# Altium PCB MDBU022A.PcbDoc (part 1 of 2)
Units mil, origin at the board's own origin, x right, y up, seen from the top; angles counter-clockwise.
Board outline 3500 x 2200 mil, 2 copper layers (Top Layer, Bottom Layer), stack 64.8 mil thick; 115 components, 70 nets, 323 pads, 476 vias.
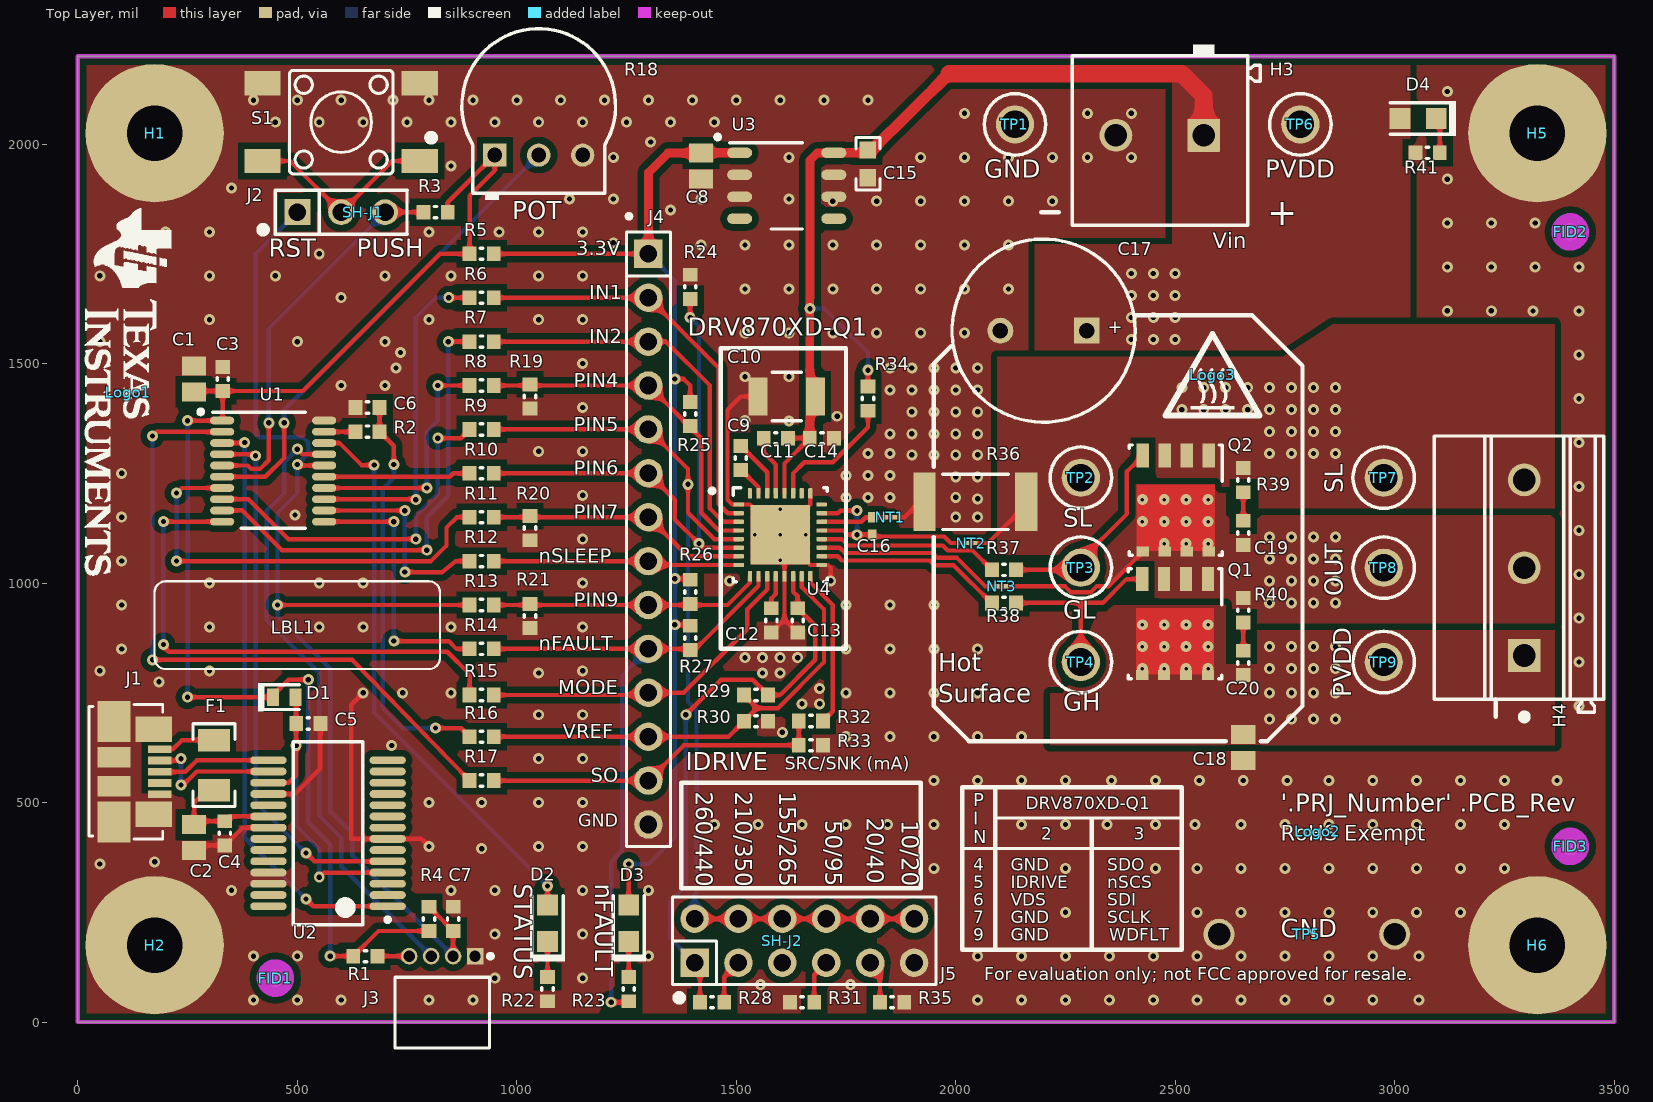
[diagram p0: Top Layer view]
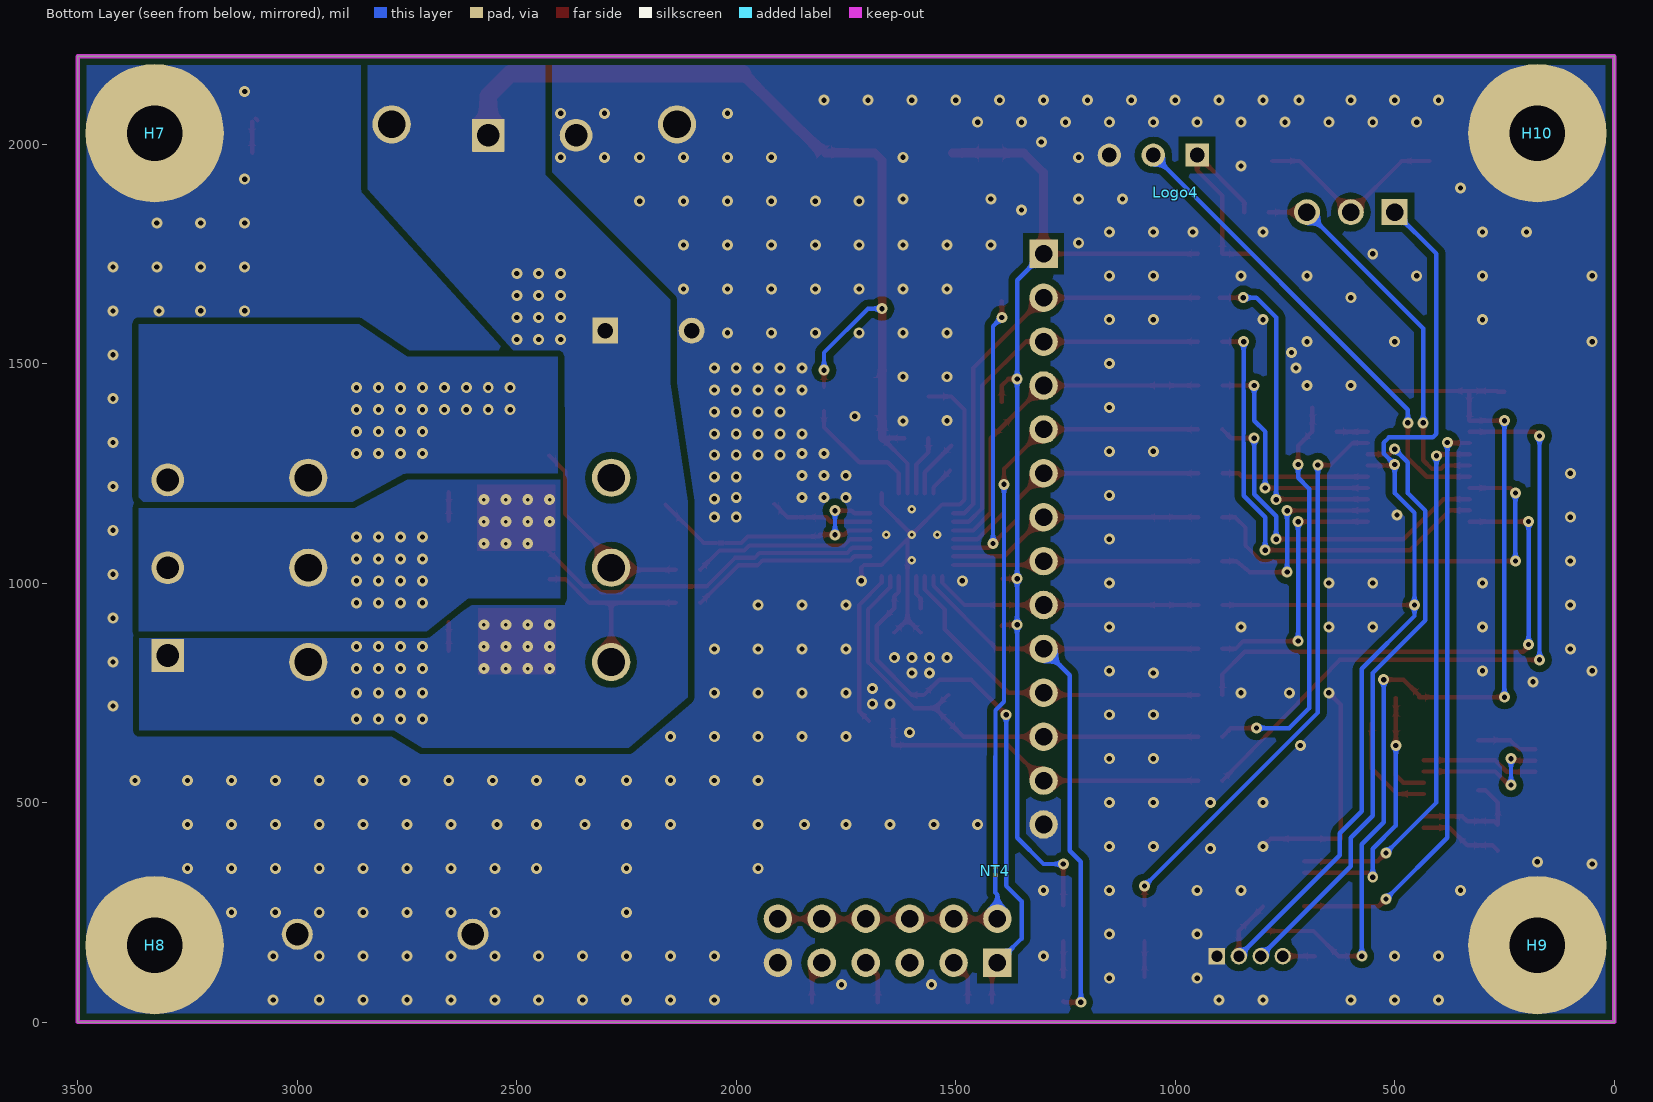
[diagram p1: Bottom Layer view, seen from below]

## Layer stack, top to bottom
Top Solder: solder mask 0.4, Solder Resist, Dk 3.5
Top Layer: signal copper 2.8
Dielectric1: core 59.2, FR-4, Dk 4.8
Bottom Layer: signal copper 2.8
Bottom Solder: solder mask 0.4, Solder Resist, Dk 3.5

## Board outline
0,0 0,2200 3500,2200 3500,0

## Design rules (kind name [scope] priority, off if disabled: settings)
AcuteAngle [All] p1: minimum=4.50000000000000E+0001 checktracksonly=FALSE
AssemblyTestPointUsage [All] p1: valid=2
Clearance Clearance_Keepouts [((IsTrack Or IsArc) And Not InPoly) And IsFree and IsKeepOut vs ((IsTrack Or IsArc) And Not InPoly) And IsFree and IsKeepOut] p1: gap=0
Clearance Clearance_BoardEdge_MountingHoles [OnCopper and InComponentClass('Mounting Holes') vs IsKeepOut] p2: gap=10
Clearance Clearance_BoardEdge_Poly [OnCopper and InPoly vs IsKeepOut] p3: gap=15
Clearance Clearance_BoardEdge [OnCopper and Not InComponentClass('Logo') and not InComponentClass('FiducialMark') and not InRegion(1000,500,4000,800) and Not IsKeepout vs IsKeepOut] p4: gap=15
Clearance Clearance_Poly [InPolygon] p5: gap=15
Clearance [All] p6: gap=7
ComponentClearance ComponentClearance_MountingHoles_FiducialMarks [InComponentClass('Mounting Holes') vs InComponentClass('FiducialMark')] p1: gap=10 collisioncheckmode=3 verticalgap=10 showdistances=FALSE
ComponentClearance ComponentClearance_Shunt [InComponentClass('Header') vs InComponentClass('Shunt')] p2: gap=0 collisioncheckmode=3 verticalgap=0 showdistances=FALSE
ComponentClearance ComponentClearance_Logo [InComponentClass('Logo')] p3: gap=10 collisioncheckmode=3 verticalgap=10 showdistances=FALSE
ComponentClearance ComponentClearance_ScrewToNut [(HasFootprint('NY PMS 440 0025 PH')) vs (HasFootprint('Keystone_1902C'))] p4: gap=5 collisioncheckmode=3 verticalgap=10 showdistances=FALSE
ComponentClearance ComponentClearance_MountingHoles [InComponentClass('Mounting Holes')] p5: gap=10 collisioncheckmode=3 verticalgap=100000 showdistances=FALSE
ComponentClearance ComponentClearance_SmallPassives [HasFootprint('0201*') or HasFootprint('0402*') or HasFootprint('0508') or HasFootprint('0603*') or HasFootprint('0612') or HasFootprint('0805*') or HasFootprint('0815*') or HasFootprint('0830*') or HasFootprint('1206*') or HasFootprint('1210*') or HasFootprint('1808*') or HasFootprint('1812*') or HasFootprint('1825*') or HasFootprint('2010*') or HasFootprint('2220*') or HasFootprint('2225*') or HasFootprint('2512*') or HasFootprint('2728*') or HasFootprint('3518*') vs HasFootprint('0201*') or HasFootprint('0402*') or HasFootprint('0508') or HasFootprint('0603*') or HasFootprint('0612') or HasFootprint('0805*') or HasFootprint('0815*') or HasFootprint('0830*') or HasFootprint('1206*') or HasFootprint('1210*') or HasFootprint('1808*') or HasFootprint('1812*') or HasFootprint('1825*') or HasFootprint('2010*') or HasFootprint('2220*') or HasFootprint('2225*') or HasFootprint('2512*') or HasFootprint('2728*') or HasFootprint('3518*')] p6: gap=10 collisioncheckmode=3 verticalgap=10 showdistances=FALSE
ComponentClearance ComponentClearance_THtoSMT [IsThruComponent vs IsSMTComponent] p7: gap=10 collisioncheckmode=3 verticalgap=10 showdistances=FALSE
ComponentClearance ComponentClearance_THtoTH [IsThruComponent vs IsThruComponent] p8: gap=10 collisioncheckmode=3 verticalgap=10 showdistances=FALSE
ComponentClearance [All] p9: gap=10 collisioncheckmode=3 verticalgap=10 showdistances=FALSE
DiffPairsRouting [All] p1: maxlimit=100 minlimit=10 mostfreqgap=10 toplayer_minwidth=15 toplayer_maxwidth=15 toplayer_prefwidth=15 bottomlayer_minwidth=15 bottomlayer_maxwidth=15 bottomlayer_prefwidth=15 maxuncoupledlength=1000
FabricationTestPointUsage TestPointUsage [All] p1: valid=2 allowmultiple=FALSE
FabricationTestpoint Testpoint [All] p1: side=3 testpointundercomponent=TRUE minsize=40 maxsize=100 preferedsize=60 minholesize=0 maxholesize=40 preferedholesize=32 testpointgrid=1 allowsidetop=TRUE allowsidebottom=TRUE usegrid=TRUE gridtolerance=0.01
FanoutControl Fanout_LCC [IsLCC] p1: bgadir=Out bgaviamode=Centered fanoutstyle=Auto fanoutdirection=Alternating viagrid=1 // Fanout_LCC (Default Rule)
FanoutControl Fanout_BGA [IsBGA] p2: bgadir=Out bgaviamode=Centered fanoutstyle=Auto fanoutdirection=Alternating viagrid=1 // Fanout_BGA (Default Rule)
FanoutControl Fanout_Default [All] p4: bgadir=Out bgaviamode=Centered fanoutstyle=Auto fanoutdirection=Alternating viagrid=1 // Fanout_Default (Default Rule)
FanoutControl Fanout_Small [(CompPinCount < 5)] p5: bgadir=Out bgaviamode=Centered fanoutstyle=Auto fanoutdirection=OutThenIn viagrid=1 // Fanout_Small (Default Rule)
HoleSize [All] p1: absolutevalues=TRUE maxlimit=251 minlimit=7 maxpercent=80.000 minpercent=20.000
MinimumAnnularRing MinimumAnnularRing_ThermalPadVias [IsVia and InAnyComponent] p1: minimumring=5.91
MinimumAnnularRing [All] p2: minimumring=5
MinimumSolderMaskSliver MinimumSolderMaskSliver_Logo [InComponentClass('Logo') vs InComponentClass('Logo')] p1: minsoldermaskwidth=0.7
MinimumSolderMaskSliver [All] p2: minsoldermaskwidth=3.94
PlaneConnect [All] p1: planeconnectstyle=Relief reliefexpansion=10 reliefentries=4 reliefconductorwidth=10 reliefairgap=10
PolygonConnect PolygonConnect_2 [All vs IsNamedPolygon('SL')] p1: connectstyle=Direct reliefconductorwidth=10 reliefentries=4 polygonreliefangle="90 Angle" airgapwidth=10
PolygonConnect PolygonConnect_1 [All vs IsNamedPolygon('SL')] p2: connectstyle=Relief reliefconductorwidth=10 reliefentries=4 polygonreliefangle="90 Angle" airgapwidth=10
PolygonConnect [All] p3: connectstyle=Direct reliefconductorwidth=10 reliefentries=4 polygonreliefangle="90 Angle" airgapwidth=10
RoutingVias ThermalPadVias [IsVia and InAnyComponent] p1: holewidth=7.87 width=19.68 viastyle="Through Hole" minholewidth=7 minwidth=19.68 maxholewidth=12.99 maxwidth=23.62
RoutingVias [All] p2: holewidth=16 width=34 viastyle="Through Hole" minholewidth=7 minwidth=25 maxholewidth=40 maxwidth=65
SilkToBoardRegionClearance [Not ((IsComment or IsDesignator) And (Hide <> 'False')) and not InRegion(1000,500,4000,800)] p1:
SilkToSilkClearance SilkToSilkClearance_Pb-FreeLogo [(HasFootprint('Pb-Free_Overlay_Medium') OR HasFootprint('Pb-Free_Overlay_Small')) vs (HasFootprint('Pb-Free_Overlay_Medium') OR HasFootprint('Pb-Free_Overlay_Small'))] p1: silktosilkclearance=0
SilkToSilkClearance [All] p2: silktosilkclearance=4
SilkToSolderMaskClearance SilkToComonentPadClearance [IsPad and InAnycomponent] p1: minsilkscreentomaskgap=5 clearancetoexposedcopper=TRUE
SilkToSolderMaskClearance "Silk to Solder Mask Opening" [All] p2: minsilkscreentomaskgap=4 clearancetoexposedcopper=FALSE
SolderMaskExpansion [All] p1: expansion=1.97
Width [All] p1: maxlimit=100 minlimit=6 preferedwidth=10 checkconnectedcopper=TRUE
15 further rules are at their usual default settings.

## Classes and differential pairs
component class Shunt: SH-J1 SH-J2
component class Header: J2 J4 J5
component class MDBU022: C1 C2 C3 C4 C5 C6 C7 C8 C9 C10 C11 C12 C13 C14 C15 C16 C17 C18 C19 C20 D1 D2 D3 D4 F1 H3 H4 J1 J2 J3 J4 J5 NT1 NT2 NT3 NT4 Q1 Q2 R1 R2 R3 R4 R5 R6 R7 R8 R9 R10 R11 R12 R13 R14 R15 R16 R17 R18 R19 R20 R21 R22 R23 R24 R25 R26 R27 R28 R29 R30 R31 R32 R33 R34 R35 R36 R37 R38 R39 R40 R41 S1 SH-J1 SH-J2 TP1 TP2 TP3 TP4 TP5 TP6 TP7 TP8 TP9 U1 U2 U3 U4
component class Label: LBL1
component class AssemblyNote: ZZ1 ZZ2 ZZ3 ZZ4
component class FiducialMark: FID1 FID2 FID3
component class MDBU022_Hardware: FID1 FID2 FID3 H1 H2 H5 H6 H7 H8 H9 H10 LBL1 Logo1 Logo2 Logo3 Logo4 ZZ1 ZZ2 ZZ3 ZZ4
component class Logo: Logo1
component class "Mounting Holes": H1 H2 H5 H6

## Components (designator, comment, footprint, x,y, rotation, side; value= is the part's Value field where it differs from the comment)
C1 "C2012X7R1A475M125AC" 0805L 265,1465 r90 top
C2 "C2012X7R1A475M125AC" 0805L 265,420 r270 top
C3 "C0603C104K8RACTU" 0603L 330,1465 r90 top
C4 "C0603C104K8RACTU" 0603L 335,430 r270 top
C5 "C0603C104K8RACTU" 0603L 525,680 r0 top
C6 "GRM188R70J105KA01D" 0603L 660,1400 r180 top
C7 "GRM188R71C102KA01D" 0603L 855,235 r90 top
C8 "JMK212BJ226KG-T" 0805L 1420,1950 r270 top
C9 "C1608X7R1H104K080AA" 0603L 1510,1285 r270 top
C10 "C3225X7S1H106K250AB" 1210_280 1615,1425 r180 top
C11 "C1608X7R1C105K080AC" 0603L 1590,1330 r0 top
C12 "GRM188R70J105KA01D" 0603L 1580,915 r90 top
C13 "GRM188R70J105KA01D" 0603L 1640,915 r270 top
C14 "C1608X7R1H104K080AA" 0603L 1695,1330 r0 top
C15 "C1608X7R1H104K080AA" 0603 1800,1955 r270 top
C16 "GRM155R71C102KA01D" 0402L 1810,1130 r90 top
C17 "ECA-1HM471" M_1000x2000 2200,1575 r180 top
C18 "GRM21BR71H105KA12L" 0805L 2655,625 r270 top
C19 "C1608X7R1H103K080AA" 0603L 2655,1114.45 r90 top
C20 "C1608X7R1H103K080AA" 0603L 2655,818.05 r90 top
D1 "CD0603-B0230" Diode_0603 470,740 r0 top
D2 "LTST-C171GKT" LED_LTST-C171 1070,225 r270 top
D3 "LTST-C170KRKT" LED_LTST-C170 1255,225 r270 top
D4 "LTST-C171GKT" LED_LTST-C171 3053.19,2058.27 r0 top
F1 "1206L050/15YR" 1206 310,585 r90 top
FID1 "Fiducial" Fiducial10-20 450,100 r0 top
FID2 "Fiducial" Fiducial10-20 3400,1800 r0 top
FID3 "Fiducial" Fiducial10-20 3400,400 r0 top
H1 "NY PMS 440 0025 PH" "NY PMS 440 0025 PH" 175,2025 r0 top
H2 "NY PMS 440 0025 PH" "NY PMS 440 0025 PH" 175,175 r0 top locked
H3 "1715721" PhoenixContact_1715721 2465,2020 r180 top
H4 "1715734" Phoenix_1715734 3295.15,1035 r90 top
H5 "NY PMS 440 0025 PH" "NY PMS 440 0025 PH" 3325,2025 r0 top
H6 "NY PMS 440 0025 PH" "NY PMS 440 0025 PH" 3325,175 r0 top
H7 "1902C" Keystone_1902C#1 3325,2025 r180 bottom locked
H8 "1902C" Keystone_1902C#1 3325,175 r180 bottom locked
H9 "1902C" Keystone_1902C#2 175.36,175 r180 bottom locked
H10 "1902C" Keystone_1902C#1 175,2025 r180 bottom locked
J1 "0473460001" CONN_47346-0001 25,570 r90 top
J2 "PEC03SAAN" CONN_PEC03SAAN 600,1845 r0 top
J3 "851-43-004-20-001000" CONN_851-43-004-20-001000 830,150 r0 top
J4 "TSW-114-07-G-S" TSW-114-07-G-S 1300,1100 r270 top
J5 "PEC06DAAN" CONN_PEC06DAAN 1655,185 r0 top
LBL1 "Size: 0.65\" x 0.20 \"" Label_650x200 500,904.1 r0 top
Logo1 "Texas Instruments" TI_Stacked_Overlay_Small 114.35,1435 r270 top
Logo2 "EU RoHS Exempt Logo" EURoHS_Exempt_60mil 2825,435 r0 top
Logo3 "CAUTION HOT SURFACE" IEC_HotSurface_Small 2585,1475 r0 top
Logo4 "FCC disclaimer" FCC_disclaimer 999.22,1890.48 r180 bottom
NT1 "Net-Tie" Net-Tie_10mil 1850.76,1150 r0 top net-tie
NT2 "Net-Tie" Net-Tie_10mil 2035,1091.25 r180 top net-tie
NT3 "Net-Tie" Net-Tie_10mil 2105,992.35 r0 top net-tie
NT4 "Net-Tie" Net-Tie_10mil 1410,345 r270 bottom net-tie
Q1 "CSD18540Q5B" TRANS_NexFET_Q5B 2499.65,899.79 r270 top
Q2 "CSD18540Q5B" TRANS_NexFET_Q5B 2501.18,1181.22 r270 top
R1 "CRCW06030000Z0EA" 0603L 655,150 r180 top
R2 "CRCW060310K0JNEA" 0603L 660,1345 r0 top
R3 "CRCW060347K0JNEA" 0603L 815,1845 r0 top
R4 "CRCW060347K0JNEA" 0603L 800,235 r270 top
R5 "CRCW06030000Z0EA" 0603L 920,1750 r180 top
R6 "CRCW06030000Z0EA" 0603L 920,1650 r180 top
R7 "CRCW06030000Z0EA" 0603L 920,1550 r180 top
R8 "CRCW06030000Z0EA" 0603L 920,1450 r180 top
R9 "CRCW06030000Z0EA" 0603L 920,1350 r180 top
R10 "CRCW06030000Z0EA" 0603L 920,1250 r180 top
R11 "CRCW06030000Z0EA" 0603L 920,1150 r180 top
R12 "CRCW06030000Z0EA" 0603L 920,1050 r180 top
R13 "CRCW06030000Z0EA" 0603L 920,950 r180 top
R14 "CRCW06030000Z0EA" 0603L 920,850 r180 top
R15 "CRCW06030000Z0EA" 0603L 920,745 r180 top
R16 "CRCW06030000Z0EA" 0603L 920,650 r180 top
R17 "CRCW06030000Z0EA" 0603L 920,550 r180 top
R18 "3352T-1-503LF" Bourns_3352T 1050,1975 r0 top
R19 "CRCW06030000Z0EA" 0603L 1030,1425 r90 top
R20 "CRCW06030000Z0EA" 0603L 1030,1125 r90 top
R21 "CRCW06030000Z0EA" 0603L 1030,925 r90 top
R22 "CRCW0603330RJNEA" 0603L 1070,75 r90 top
R23 "CRCW0603330RJNEA" 0603L 1255,75 r90 top
R24 "CRCW06030000Z0EA" 0603L 1395,1675 r270 top
R25 "RC0603JR-07750RL" 0603L 1395,1385 r90 top
R26 "CRCW060310K0JNEA" 0603L 1395,980 r270 top
R27 "CRCW060310K0JNEA" 0603L 1395,875 r270 top
R28 "CRCW060368K0JNEA" 0603L 1445,45 r180 top
R29 "CRCW06030000Z0EA" 0603L 1545,745 r180 top
R30 "CRCW06030000Z0EA" 0603L 1545,685 r0 top
R31 "CRCW0603200KJNEA" 0603L 1650,45 r0 top
R32 "CRCW06037K50FKEA" 0603L 1670,685.67 r180 top
R33 "CRCW060310K0FKEA" 0603L 1670,630.67 r180 top
R34 "CRCW06030000Z0EA" 0603L 1800,1420 r270 top
R35 "CRCW060333K0JNEA" 0603L 1855,45 r180 top
R36 "CSR2512C0R01F" 2512 2045,1185 r0 top
R37 "CRCW06030000Z0EA" 0603L 2110,1030 r0 top
R38 "CRCW06030000Z0EA" 0603L 2110,954.7 r0 top
R39 "RT0603BRD07100RL" 0603L 2655,1234.45 r270 top
R40 "RT0603BRD07100RL" 0603L 2655,938.05 r270 top
R41 "CRCW06034K99FKEA" 0603L 3075,1980 r0 top
S1 "FSM4JSMA" SW_FSM4JSMA 600,2050 r270 top
SH-J1 "969102-0000-DA" SNT-100-BK-G 650,1845 r180 top
SH-J2 "969102-0000-DA" SNT-100-BK-G 1605,185 r90 top
TP1 "5006" Keystone5006 2135,2045 r0 top
TP2 "5007" Keystone5007 2285,1240 r0 top
TP3 "5007" Keystone5007 2285,1035 r0 top
TP4 "5007" Keystone5007 2285,820 r0 top
TP5 "D3082-05" Harwin_D3082-05 2800,200 r180 top
TP6 "5005" Keystone5005 2785,2045 r0 top
TP7 "5007" Keystone5007 2975,1240 r90 top
TP8 "5007" Keystone5007 2975,1035 r90 top
TP9 "5005" Keystone5005 2975,820 r90 top
U1 "MSP430G2553IPW20" PW0020A_N 445,1255 r0 top
U2 "FT232RL" SSOP28_N 570,430 r180 top
U3 "LM9036QMX-3.3/NOPB" D0008A_N 1615,1905 r0 top
U4 "DRV8702DQRHBRQ1" RHB0032E 1600,1110 r0 top
ZZ1 "This Assembly Note is for PCB labels only" AssemblyNoteLabel 185,2598 r0 top
ZZ2 "This Assembly Note will show in the PcbDoc and associated outputs" AssemblyNote 185,2489.11 r0 top
ZZ3 "This Assembly Note will show in the PcbDoc and associated outputs" AssemblyNote 185,2400.56 r0 top
ZZ4 "This Assembly Note will show in the PcbDoc and associated outputs" AssemblyNote 185,2312 r0 top

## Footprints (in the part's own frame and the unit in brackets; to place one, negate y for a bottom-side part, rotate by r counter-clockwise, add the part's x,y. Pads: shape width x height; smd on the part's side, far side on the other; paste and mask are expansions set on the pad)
0402L [mm] "0402 from SM-752 data"
  rect 0.6x0.5 smd: 1(-0.5,0) 2(0.5,0)
  body extent -0.55,-0.3 0.55,0.3, height 0.6
0603 [mm] "0603 from SM-752 data"
  rect 1x0.95 smd: 1(-0.8,0) 2(0.8,0)
  silkscreen extent -1.52,-0.69 1.52,0.69, body extent -0.87,-0.47 0.87,0.47, height 1
0603L [mm] "0603 from SM-752 data"
  rect 0.8x0.85 smd: 1(-0.7,0) 2(0.7,0)
  silkscreen extent -0.07,-0.33 0.07,0.33, body extent -0.87,-0.47 0.87,0.47, height 1
0805L [mm] "0805 from SM-752 data"
  rect 1.1x1.4 smd: 1(-0.75,0) 2(0.75,0)
  body extent -1.1,-0.72 1.1,0.72, height 1.45
1206 [mm] "1206 from SM-752 data"
  rect 1.3x1.85 smd: 1(-1.45,0) 2(1.45,0)
  silkscreen extent -2.4,-1.21 2.4,1.21, body extent -1.7,-0.9 1.7,0.9, height 1.35
1210_280 [mm] "SMD, 2-Leads, Body 3.6x2.8mm, Height 2.8mm"
  rect 1.1x2.2 smd: 1(-1.65,0) 2(1.65,0)
  silkscreen extent -0.84,-1.4 0.84,1.4, body extent -1.8,-1.4 1.8,1.4, height 2.8
2512 [mm] "Chip Resistor, Body 6.3x3.2mm, IPC Medium Density"
  rect 1.3x3.4 smd: 1(-2.95,0) 2(2.95,0)
  silkscreen extent -1.9,-1.6 1.9,1.6, body extent -3.22,-1.67 3.22,1.67, height 0.71
AssemblyNote [mil] "Assembly Note"
AssemblyNoteLabel [mil] "Assembly Note for PCB Labels"
Bourns_3352T [mm] "TH, 3-Leads, Body 9.53x8.89mm, Pitch 2.54mm"
  rect 1.35x1.35 hole 0.85: 1(-2.54,0)
  round 1.35 hole 0.85: 2(0,0) 3(2.54,0)
  silkscreen extent -4.44,-2.6 4.44,7.31, body extent -4.44,-2.21 4.45,7.32, height 3.81
CONN_851-43-004-20-001000 [mm] "MILL-MAX"
  rect 0.95x0.95 hole 0.65: 1(1.905,0)
  round 0.95 hole 0.65: 2(0.635,0) 3(-0.635,0) 4(-1.905,0)
  silkscreen extent -2.73,-5.31 2.73,-1.22, body extent -2.73,-5.31 2.73,0.23, height 2.23
CONN_47346-0001 [mm] "MOLEX"
  rect 0.45x1.38 smd: 1(1.3,-4.105) 2(0.65,-4.105) 3(0,-4.105) 4(-0.65,-4.105) 5(-1.3,-4.105)
  rect 1.475x2.1 smd: 6(-2.462,-3.755) 11(2.463,-3.75)
  rect 2.375x1.9 smd: 7(-2.912,-1.45) 10(2.912,-1.45)
  rect 1.175x1.9 smd: 8(-0.837,-1.45) 9(0.837,-1.45)
  silkscreen extent -3.9,-4.28 3.9,0, body extent -3.99,-4.43 3.99,1, height 2.72
CONN_PEC03SAAN [mm] "SULLINS"
  rect 1.5x1.5 hole 1.016: 1(-2.54,0)
  round 1.5 hole 1.016: 2(0,0) 3(2.54,0)
  silkscreen extent -4.72,-1.27 3.81,1.27, body extent -3.84,-1.3 3.84,1.3, height 8.38
CONN_PEC06DAAN [mm] "SULLINS"
  rect 1.65x1.65 hole 1.016 mask+0: 1(-6.35,-1.27)
  round 1.65 hole 1.016 mask+0: 2(-6.35,1.27) 3(-3.81,-1.27) 4(-3.81,1.27) 5(-1.27,-1.27) 6(-1.27,1.27) 7(1.27,-1.27) 8(1.27,1.27) 9(3.81,-1.27) 10(3.81,1.27) 11(6.35,-1.27) 12(6.35,1.27)
  silkscreen extent -7.62,-3.51 7.62,2.54, body extent -7.62,-2.54 7.62,2.54, height 8.38
D0008A_N [mm] "SOIC, 8-Leads, Body 4.9x3.9mm, Pitch 1.27mm, IPC Medium Density"
  oval 1.45x0.6 smd: 1(-2.725,1.905) 2(-2.725,0.635) 3(-2.725,-0.635) 4(-2.725,-1.905) 5(2.725,-1.905) 6(2.725,-0.635) 7(2.725,0.635) 8(2.725,1.905)
  silkscreen extent -3.3,-2.5 0.9,2.5, body extent -3,-2.45 3,2.45, height 1.63
Diode_0603 [mm] "Based on Bourns recommended land pattern Rev 10/09"
  rect 0.7x1 smd: 1(-0.65,0) 2(0.65,0)
  silkscreen extent -1.5,-0.8 0.9,0.8, body extent -0.9,-0.5 0.9,0.5, height 0.85
EURoHS_Exempt_60mil [mil] "EU RoHS Exempt symbol"
FCC_disclaimer [mil]
Fiducial10-20 [mm]
  round 1 smd mask+0.5: 1(0,0)
  Top Layer keep-out circle w1.178: c0,0 r0.5
Harwin_D3082-05 [mm] "Shorting Plug, 10.16mm spacing, TH"
  round 1.8 hole 1.3: 1(-5.08,0) 2(5.08,0)
  body extent -5.6,-0.52 5.61,0.52, height 6.63
IEC_HotSurface_Small [mil]
  silkscreen extent -107,-93 107,92
Keystone5005 [mil] "Keystone Compact loops"
  round 87 hole 63: 1(0,0)
  silkscreen extent -70,-70 70,70, body extent -63,-63 62,63, height 225
Keystone5006 [mil] "Keystone Compact loops"
  round 87 hole 63: 1(0,0)
  silkscreen extent -70,-70 70,70, body extent -63,-63 62,63, height 225
Keystone5007 [mil] "Keystone Compact loops"
  round 87 hole 63: 1(0,0)
  silkscreen extent -70,-70 70,70, body extent -63,-63 62,63, height 225
Keystone_1902C#1 [mil] "Hex Standoff, 4-40 threaded, nylon"
  body extent -145,-126 146,126, height 501
Keystone_1902C#2 [mil] "Hex Standoff, 4-40 threaded, nylon"
  round 1 on Mech4: 0(0,0)
  body extent -145,-126 146,126, height 501
Label_650x200 [mil] "Thermal Transfer Label"
  silkscreen extent -325,-100 325,100, body extent -325,-100 325,100, height 1
LED_LTST-C170 [mm] "LITE-ON"
  rect 1.2x1.2 smd: 1(-1.05,0) 2(1.05,0)
  silkscreen extent -1.6,-1 2.2,1, body extent -1.05,-0.67 1.05,0.67, height 1.1
LED_LTST-C171 [mm] "LITE-ON"
  rect 1.2x1.2 smd: 1(-1.05,0) 2(1.05,0)
  silkscreen extent -1.6,-1 2.2,1, body extent -1.05,-0.67 1.05,0.67, height 0.8
M_1000x2000 [mm] "Panasonic"
  rect 1.5x1.5 hole 0.9: 1(-2.5,0)
  round 1.5 hole 0.9: 2(2.5,0)
  silkscreen extent -5.3,-5.3 5.3,5.3, body extent -5.21,-5.24 5.24,5.24, height 22.01
Net-Tie_10mil [mil] "10mil net tie, no solder mask opening, no solder paste"
  rect 10x10 smd paste-5 mask-5: 1(-10,0) 2(10,0)
  Top Layer region: -6,5 6,5 6,-5 -6,-5
"NY PMS 440 0025 PH" [mm] "4-40 nylon screw and mounting hole"
  round 8 hole 3.2: 1(0,0)
  body extent -3.3,-3.3 3.3,3.3, height 2.69
Phoenix_1715734 [mm] "Phoenix"
  rect 1.9x1.9 hole 1.321: 1(-5.08,0)
  round 1.9 hole 1.321: 2(0,0) 3(5.08,0)
  silkscreen extent -8.76,-4.6 7.62,5.2, body extent -8.36,-4.6 7.62,5.2, height 14.2
PhoenixContact_1715721 [mm] "Phoenix Contact 1715721 used on LM3445 design from Longmont"
  rrect5% 1.905x1.905 hole 1.3: 1(-2.54,0)
  round 1.9 hole 1.3: 2(2.54,0)
  silkscreen extent -5.82,-5.25 5.08,5.2, body extent -5.82,-4.6 5.08,5.2, height 14.2
PW0020A_N [mm] "TSOP, 20-Leads, Body 6.5x4.4mm, Pitch 0.65mm, IPC Medium Density"
  oval 1.4x0.45 smd: 1(-2.95,2.925) 2(-2.95,2.275) 3(-2.95,1.625) 4(-2.95,0.975) 5(-2.95,0.325) 6(-2.95,-0.325) 7(-2.95,-0.975) 8(-2.95,-1.625) 9(-2.95,-2.275) 10(-2.95,-2.925) 11(2.95,-2.925) 12(2.95,-2.275) 13(2.95,-1.625) 14(2.95,-0.975) 15(2.95,-0.325) 16(2.95,0.325) 17(2.95,0.975) 18(2.95,1.625) 19(2.95,2.275) 20(2.95,2.925)
  silkscreen extent -3.5,-3.3 1.85,3.4, body extent -3.21,-3.25 3.21,3.25, height 1
RHB0032E [mm] "QFN, 32-Leads, Body 5x5mm, Pitch 0.5mm, Thermal Pad 3.45x3.45mm, TI Recommended"
  rrect40% 0.6x0.25 smd: 1(-2.4,1.75) 2(-2.4,1.25) 3(-2.4,0.75) 4(-2.4,0.25) 5(-2.4,-0.25) 6(-2.4,-0.75) 7(-2.4,-1.25) 8(-2.4,-1.75) 17(2.4,-1.75) 18(2.4,-1.25) 19(2.4,-0.75) 20(2.4,-0.25) 21(2.4,0.25) 22(2.4,0.75) 23(2.4,1.25) 24(2.4,1.75)
  rrect40% 0.25x0.6 smd: 9(-1.75,-2.4) 10(-1.25,-2.4) 11(-0.75,-2.4) 12(-0.25,-2.4) 13(0.25,-2.4) 14(0.75,-2.4) 15(1.25,-2.4) 16(1.75,-2.4) 25(1.75,2.4) 26(1.25,2.4) 27(0.75,2.4) 28(0.25,2.4) 29(-0.25,2.4) 30(-0.75,2.4) 31(-1.25,2.4) 32(-1.75,2.4)
  rrect3% 3.45x3.45 smd paste-1.725: 33(0,0)
  rrect7% 1.49x1.49 on Top Paste: ""(-0.845,-0.845) ""(-0.845,0.845) ""(0.845,-0.845) ""(0.845,0.845)
  silkscreen extent -2.72,-2.73 2.72,2.73, body extent -2.57,-2.57 2.58,2.58, height 1.01
SNT-100-BK-G [mil] "Samtec STEP model"
  round 1 on Mech3: 0(0,0)
  body extent -100,-50 100,50, height 344
SSOP28_N [mm] "SOP, 28-Leads, Body 10.2x5.3mm, Pitch 0.65mm, IPC Medium Density"
  oval 2.1x0.45 smd: 1(-3.45,4.225) 2(-3.45,3.575) 3(-3.45,2.925) 4(-3.45,2.275) 5(-3.45,1.625) 6(-3.45,0.975) 7(-3.45,0.325) 8(-3.45,-0.325) 9(-3.45,-0.975) 10(-3.45,-1.625) 11(-3.45,-2.275) 12(-3.45,-2.925) 13(-3.45,-3.575) 14(-3.45,-4.225) 15(3.45,-4.225) 16(3.45,-3.575) 17(3.45,-2.925) 18(3.45,-2.275) 19(3.45,-1.625) 20(3.45,-0.975) 21(3.45,-0.325) 22(3.45,0.325) 23(3.45,0.975) 24(3.45,1.625) 25(3.45,2.275) 26(3.45,2.925) 27(3.45,3.575) 28(3.45,4.225)
  silkscreen extent -3.57,-5.3 2,5.3, body extent -2.7,-5.3 2.7,5.3, height 2
SW_FSM4JSMA [mm] "Alcoswitch"
  rect 1.4x2.1 smd: 1(2.25,4.55) 2(2.25,-4.55) 3(-2.25,4.55) 4(-2.25,-4.55)
  silkscreen extent -3,-3 3,5.4, body extent -3,-5 3,5, height 5.1
TI_Stacked_Overlay_Small [mil]
  silkscreen extent -418,-98 418,98
TRANS_NexFET_Q5B [mm] "TI recommended land pattern (nominal) November 2012"
  rect 1.372x0.71 smd paste-0.4: 1(-2.776,1.905) 2(-2.776,0.635) 3(-2.776,-0.635) 4(-2.776,-1.905)
  rect 0.59x0.71 smd paste-0.3: 5(2.776,-1.905) 6(2.776,-0.635) 7(2.776,0.635) 8(2.776,1.905)
  Top Layer region: -1.105,-2.259 2.745,-2.259 2.745,2.261 -1.105,2.261
  silkscreen extent -3.38,-2.7 3,2.7, body extent -3.23,-2.55 2.87,2.55, height 1.06
TSW-114-07-G-S [mm] "Samtec 100mil, 1x14, 230 mil above insulator"
  rect 1.65x1.65 hole 1.016 mask+0: 1(-16.51,0)
  round 1.65 hole 1.016 mask+0: 2(-13.97,0) 3(-11.43,0) 4(-8.89,0) 5(-6.35,0) 6(-3.81,0) 7(-1.27,0) 8(1.27,0) 9(3.81,0) 10(6.35,0) 11(8.89,0) 12(11.43,0) 13(13.97,0) 14(16.51,0)
  silkscreen extent -18.8,-1.27 17.78,1.27, body extent -17.78,-1.27 17.78,1.27, height 8.38

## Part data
C1 C2: "CAP, CERM, 4.7 µF, 10 V, +/- 20%, X7R, 0805"
C3 C4 C5: "CAP, CERM, 0.1 µF, 10 V, +/- 10%, X7R, 0603"
C6 C12 C13: "CAP, CERM, 1 µF, 6.3 V, +/- 10%, X7R, 0603"
C7: "CAP, CERM, 1000 pF, 16 V, +/- 10%, X7R, 0603"
C8: "CAP, CERM, 22 µF, 6.3 V, +/- 10%, X5R, 0805"
C9 C14 C15: "CAP, CERM, 0.1 µF, 50 V, +/- 10%, X7R, 0603"
C10: "CAP, CERM, 10 µF, 50 V, +/- 10%, X7S, 1210"
C11: "CAP, CERM, 1 µF, 16 V, +/- 10%, X7R, 0603"
C16: "CAP, CERM, 1000 pF, 16 V, +/- 10%, X7R, 0402"
C17: "CAP, AL, 470 µF, 50 V, +/- 20%, TH"
C18: "CAP, CERM, 1 µF, 50 V, +/- 10%, X7R, 0805"
C19 C20: "CAP, CERM, 0.01 µF, 50 V, +/- 10%, X7R, 0603"
D1: "Diode, Schottky, 35 V, 0.2 A, 0603 Diode"
D2 D4: "LED, Green, SMD"
D3: "LED, Red, SMD"
F1: "Fuse, 100 A, 15 VDC, SMD"
FID1 FID2 FID3: "Fiducial mark.  There is nothing to buy or mount."
H1 H2 H5 H6: "Machine Screw, Round, #4-40 x 1/4, Nylon, Philips panhead"
H3: "Terminal Block, 5.08 mm, 2x1, TH"
H4: "TERM BLOCK 3POS 5.08MM, TH"
H7 H8 H9 H10: "Standoff, Hex, 0.5\"L #4-40 Nylon"
J1: "Connector, Receptacle, Micro-USB Type B, R/A, Bottom Mount SMT"
J2: "Header, 100mil, 3x1, Tin, TH"
J3: "SOCKET .050\" GRID SIP 4 POS R/A, TH"
J4: "Header, 100mil, 14x1, Gold, TH"
J5: "Header, 100mil, 6x2, Tin, TH"
LBL1: library part THT-14-423-10, "Thermal Transfer Printable Labels, 0.650\" W x 0.200\" H - 10,000 per roll"
Logo1: library part TI_Logo, "Texas Instrument Corporate Signature"
Logo2: library part EURoHS_Exempt
Logo3: library part IEC_HotSurface, "IEC 61010-1 Hot Surface Warning"
Logo4: library part FCC_disclaimer, "FCC_disclaimer"
NT1 NT2 NT3 NT4: "Single point connection between nets."
Q1 Q2: "MOSFET, N-CH, 60 V, 28 A, SON 5x6mm"
R1 R5 R6 R7 R8 R9 R10 R11 R12 R13 R14 R15 R16 R17 R19 R20 R21 R24 R29 R30 R34 R37 R38: "RES, 0, 5%, 0.1 W, 0603"
R2 R26 R27: "RES, 10 k, 5%, 0.1 W, 0603"
R3 R4: "RES, 47 k, 5%, 0.1 W, 0603"
R18: "Trimming Potentiometer, 50K, 0.5W, TH"
R22 R23: "RES, 330, 5%, 0.1 W, 0603"
R25: "RES, 750, 5%, 0.1 W, 0603"
R28: "RES, 68 k, 5%, 0.1 W, 0603"
R31: "RES, 200 k, 5%, 0.1 W, 0603"
R32: "RES, 7.50 k, 1%, 0.1 W, 0603"
R33: "RES, 10.0 k, 1%, 0.1 W, 0603"
R35: "RES, 33 k, 5%, 0.1 W, 0603"
R36: "RES, 0.01, 1%, 3 W, AEC-Q200 Grade 0, 2512"
R39 R40: "RES, 100, 0.1%, 0.1 W, 0603"
R41: "RES, 4.99 k, 1%, 0.1 W, 0603"
S1: "Switch, Tactile, SPST-NO, 0.05A, 12V, SMT"
SH-J1 SH-J2: "Shunt, 100mil, Gold plated, Black"
TP1: "Test Point, Compact, Black, TH"
TP2 TP3 TP4 TP7 TP8: "Test Point, Compact, White, TH"
TP5: "1mm Uninsulated Shorting Plug, 10.16mm spacing, TH"
TP6 TP9: "Test Point, Compact, Red, TH"
U1: "16 MHz Mixed Signal Microcontroller with 16 KB Flash, 512 B SRAM and 24 GPIOs, -40 to 85 degC, 20-pin SOP (PW), Green (RoHS & no Sb/Br)"
U2: "USB to Serial UART, SSOP28"
U3: "Ultra-Low Quiescent Current Voltage Regulator, D0008A"
U4: "Automotive Half H-Bridge Gate Driver, RHB0032E (VQFN-32)"
ZZ1: library part AssemblyNoteLabel
ZZ2 ZZ3 ZZ4: library part AssemblyNote

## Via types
v1: diameter 25, hole 12, Top Layer to Bottom Layer, tented both sides, 446 vias
v2: diameter 25, hole 7.82, Top Layer to Bottom Layer, tented both sides, 23 vias
v3: diameter 19.68, hole 7.87, Top Layer to Bottom Layer, 5 vias
v4: diameter 25, hole 12, Top Layer to Bottom Layer, 2 vias

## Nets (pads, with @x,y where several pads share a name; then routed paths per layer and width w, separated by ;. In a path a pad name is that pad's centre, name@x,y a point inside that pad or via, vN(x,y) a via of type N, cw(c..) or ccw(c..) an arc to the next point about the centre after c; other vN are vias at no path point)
3.3V: C8.1 D3.1 J4.1 R5.1 R25.2 R26.1 R27.1 U3.1 | length 2488.9
  Top Layer w10: R5.1@948.05,1750 J4.1@1300,1750 ; D3.1@1255,266.34 v1(1255,360) ; v1(1360,905) 1392.56,905 R27.1@1395,902.56 ; v1(1360,1010) R26.1@1392.56,1010 ; v1(1360,1465) 1380,1465 1395,1450 R25.2@1395,1412.56 ; C8.1@1420,1979.53 C8.1@1420.47,1980
  Top Layer w20: J4.1@1300,1750 1300,1935 1344.53,1979.53 C8.1@1420,1979.53 ; C8.1@1420.47,1980 U3.1@1507.72,1980
  Bottom Layer w10: v1(1255,360) 1300,360 1360,420 v1(1360,905) v1(1360,1010) v1(1360,1465) 1360,1690 J4.1@1300,1750
3.3V_COM: C5.1 D1.2 U2.4 U2.17 | length 728.1
  Top Layer w10: U2.17@434.17,545.16 480.16,545.16 497.44,562.44 v1(497.44,630) C5.1@497.44,680 D1.2@497.44,738.15 ; v1(550,330) 560.43,340.43 U2.4@705.83,340.43
  Bottom Layer w10: v1(497.44,630) 497.44,447.56 550,395 v1(550,330)
3.3V_MCU: C1.1 C3.1 D1.1 R1.2 R3.2 R4.2 R5.2 R18.1 U1.1 | length 3164.6
  Top Layer w10: v1(250,740) D1.1@444.41,740 444.41,744.41 480,780 v1(525,780) ; v1(250,1370) U1.1@328.7,1370 ; C1.1@250,1435.47 C1.1@265,1435.47 266.97,1437.44 C3.1@330,1437.44 ; U1.1@330,1371.3 C3.1@330,1437.44 ; v1(575,150) R1.2@627.44,150 684.88,207.44 R4.2@800,207.44 ; R3.2@842.56,1845 842.56,1867.56 R18.1@950,1975 950,1940 892.44,1882.44 R5.2@892.44,1750 825,1750 512.44,1437.44 C3.1@330,1437.44
  Bottom Layer w10: v1(250,740) v1(250,1370) ; v1(525,780) 525,455 575,405 v1(575,150)
5V_USB: C2.1 C4.1 F1.1 U2.20 | length 284
  Top Layer w10: F1.1@310,527.91 292.91,527.91 265,500 C2.1@265,449.53 273.03,457.56 C4.1@335,457.56 345.83,468.39 U2.20@434.17,468.39
AVDD: C13.1 J5.1 R28.2 R29.1 U4.14 | length 1284.6
  Top Layer w10: v1(1385,700) 1465,780 1537.56,780 R29.1@1572.56,745 1600,745 1680,825 1680,902.56 C13.1@1640,942.56 1640,970 1629.53,980.47 U4.14@1629.53,1015.51 ; J5.1@1405,135 1417.44,122.56 R28.2@1417.44,45
  Bottom Layer w10: v1(1385,700) 1385,310 1350,275 1350,190 J5.1@1405,135
DM: J1.2 U2.16 | length 333.7
  Top Layer w10: J1.2@180,595.59 230.59,595.59 v1(235,600) ; v1(235,540) 240.28,540 271.03,570.75 U2.16@434.17,570.75
  Bottom Layer w10: v1@235,535 v1(235,540) v1(235,600)
DP: J1.3 U2.15 | length 265.1
  Top Layer w10: J1.3@180,570 245,570 271.34,596.34 U2.15@434.17,596.34
DVDD: C12.2 U4.12 | length 77.2
  Top Layer w10: C12.2@1580,942.56 1580,965 1590.16,975.16 U4.12@1590.16,1015.51
GH: R38.1 U4.18 | length 431.9
  Top Layer w10: U4.18@1694.49,1060.79 1731.13,1060.79 1740.42,1051.5 1940.42,1051.5 1951.67,1040.25 1995.71,1040.25 2081.25,954.7 R38.1@2082.44,954.7
GL: R37.1 U4.20 | length 417
  Top Layer w10: U4.20@1694.49,1100.16 1739.84,1100.16 1754.5,1085.5 1970.46,1085.5 1981.71,1074.25 2038.19,1074.25 R37.1@2082.44,1030
GND: C1.2 C2.2 C3.2 C4.2 C5.2 C6.2 C7.2 C8.2 C10.2 C12.1 C13.2 C14.2 C15.2 C17.2 C18.2 H1.1 H2.1 H3.2 H5.1 H6.1 J1.5 J1.6 J1.7 J1.8 J1.9 J1.10 J1.11 J3.1 J4.14 J5.11 NT1.2 R18.3 R19.1 R20.1 R21.1 R22.1 R24.1 R30.2 R31.1 R33.1 R35.1 R36.1 R41.1 S1.3 S1.4 TP1.1 TP5.1 TP5.2 U1.20 U2.7 U2.18 U2.21 U2.25 U2.26 U3.2 U3.3 U3.6 U3.7 U4.1 U4.13 U4.17 U4.25 U4.33 | length 2048
  Top Layer w10: C2.2@265,390.47 276.97,402.44 C4.2@335,402.44 375.35,442.8 U2.21@434.17,442.8 ; U2.18@434.17,519.57 494.57,519.57 552.56,577.56 C5.2@552.56,680 ; v1(650,750) 622.8,722.8 622.8,417.2 U2.7@705.83,417.2 782.8,417.2 v1(800,400) ; C10.2@1561.85,1425 1510,1425 1480,1395 1480,1190 1491.1,1178.9 1531.1,1178.9 v3(1600,1110) ; C12.1@1580,887.44 1609.84,917.28 ; C13.2@1640,887.44 1639.69,887.44 1609.84,917.28 ; U4.25@1668.9,1204.49 1668.9,1178.9 v3(1600,1110) ; v1(1715,1005) 1715,1035 1708.9,1041.1 U4.17@1694.49,1041.1 1668.9,1041.1 U4.33@1609.84,1100.16 ; NT1.2@1860.76,1150 1883.17,1150 R36.1@1913.17,1180 ; v3(1600,1110) U4.33@1609.84,1100.16 ; 1609.84,917.28 U4.13@1609.84,1015.51 U4.33@1609.84,1100.16
  other v1: 400,50 500,50 600,50 800,50 900,50 2050,50 2150,50 2250,50 2350,50 2450,50 2550,50 2650,50 3055,50 2750,50.67 2850,50.67 2950,50.67 1555,85 1760,85 950,100 1150,100 400,150 500,150 1300,150 2050,150 2150,150 2250,150 2350,150 2450,150 2550,150 2650,150 2750,150 2850,150 2950,150 3055,150 950,200 1150,200 2250,250 2550,250 2650,250 2750,250 2850,250 2950,250 3050,250 3150,250 350,300 850,300 950,300 1150,300 1300,300 1950,350 2250,350 2455,350 2550,350 2650,350 2750,350 2850,350 2950,350 3050,350 3150,350 3250,350 50,360 175,365 920,395 1050,400 1150,400 1450,450 1550,450 1650,450 1750,450 1845,450 1950,450 2150,450 2250,450 2345,450 2455,450 2545,450 2650,450 2750,450 2850,450 2950,450 3050,450 3150,450 3250,450 800,500 920,500 1050,500 1150,500 1950,550 2050,550 2355,550 2455,550 2555,550 2655,550 2755,550 2850,550 2950,550 3050,550 3150,550 3250,550 3370,550 2150,550.67 2250,550.67 1050,600 1150,600 715,630 1750,650 1850,650 1950,650 2050,650 2150,650 1605,660 1050,700 1150,700 3420,720 1650,725 1690,725 740,750 850,750 1750,750 1850,750 1950,750 2050,750 1690,760 185,775 1050,795 1560,795 1600,795 50,800 300,800 1150,800 3420,820 1520,830 1560,830 1600,830 1640,830 100,850 1750,850 1850,850 1950,850 2050,850 300,900 550,900 650,900 850,900 1150,900 3420,920 100,950 1750,950 1850,950 1950,950 300,1000 550,1000 650,1000 1150,1000 1485,1005 3420,1020 100,1050 1150,1100 3420,1120 100,1150 2000,1150 2050,1150 495,1155 2050,1192.01 1750.51,1194.53 1800,1195 1850,1195 2000,1195.24 1150,1200 3420,1220 2000,1242.01 2050,1242.01 1750.51,1244.53 1800,1245 1850,1245 100,1250 1900,1292.01 1950,1292.01 2000,1292.01 2050,1292.01 1800,1295 1850,1295 1050,1300 1150,1300 3420,1320 1850,1340 1900,1340 1950,1340 2000,1340 2050,1340 1620,1369.33 1520,1370 1730,1380 1900,1390 1950,1390 2000,1390 2050,1390 1150,1400 3420,1420 1850,1440 1900,1440 1950,1440 2000,1440 2050,1440 600,1450 700,1450 1520,1470 1620,1470 725,1490 1850,1490 1900,1490 1950,1490 2000,1490 2050,1490 1150,1500 3420,1520 735,1525 50,1550 500,1550 700,1550 1520,1570 1620,1570 1720,1570 1820,1570 1920,1570 2020,1570 300,1600 800,1600 1050,1600 1150,1600 3120,1620.29 3220,1620.29 3315,1620 3420,1620 600,1650 1520,1670 1620,1670 1720,1670 1820,1670 1920,1670 2020,1670 2120,1670 50,1700 300,1700 450,1700 700,1700 850,1700 1050,1700 1150,1700 3120,1720 3220,1720 3320,1720 3420,1720 550,1750 1420,1770 1520,1770 1620,1770 1720,1770 1820,1770 1920,1770 2020,1770 2120,1770 1220,1775 200,1800 300,1800 800,1800 960,1800 1050,1800 1150,1800 3120,1820 3220,1820 3320,1820 1350,1850 1720,1870 1820,1870 1920,1870 2020,1870 2120,1870 2220,1870 1120,1875 1220,1875 1420,1875 1620,1875 350,1900 3120,1920 850,1950 1220,1970 1620,1970 1920,1970 2020,1970 2120,1970 2220,1970 2300,1970 2400,1970 1305,2005 450,2050 550,2050 650,2050 750,2050 850,2050 950,2050 1050,2050 1150,2050 1250,2050 1350,2050 1450,2050 2020,2070 2300,2070 2400,2070 400,2100 500,2100 600,2100 718.11,2100 800,2100 900,2100 1000,2100 1100,2100 1200,2100 1300,2100 1400,2100 1500,2100 1600,2100 1700,2100 1800,2100 3120,2120
  other v3: 1600,1051.93 1541.93,1110 1658.07,1110 1600,1168.07
IDRIVE: J5.2 J5.4 J5.6 J5.8 J5.10 J5.12 NT4.2 | length 602.1
  Top Layer w10: J5.2@1405,235 J5.4@1505,235 J5.6@1605,235 J5.8@1705,235 J5.10@1805,235 J5.12@1905,235
  Bottom Layer w10: J5.2@1405,235 1405,290 1410,295 NT4.2@1410,335
IN1: J4.2 R6.1 U4.2 | length 942.8
  Top Layer w10: R6.1@947.56,1650 J4.2@1300,1650 1460,1490 1460,1180 1480.79,1159.21 U4.2@1505.51,1159.21
IN1_MCU: R6.2 U1.13 | length 769.8
  Top Layer w10: U1.13@561.14,1191.02 v1@768.98,1191.02 ; v1(845,1650) R6.2@898.33,1650
  Bottom Layer w10: v1(770,1190) 770,1605 815,1650 v1(845,1650)
IN2: J4.3 R7.1 U4.3 | length 891.5
  Top Layer w10: R7.1@948.05,1550 J4.3@1300,1550 1340,1550 1440,1450 1440,1170 1470.47,1139.53 U4.3@1505.51,1139.53
IN2_MCU: R7.2 U1.9 | length 1048.1
  Top Layer w10: U1.9@328.86,1165.43 374.57,1165.43 465,1075 v1(795,1075) ; v1(844.02,1550) R7.2@892.44,1550
  Bottom Layer w10: v1(795,1075) 795,1150 844.02,1199.02 844.02,1319.37 844.5,1319.85 844.5,1340.15 844.02,1340.63 844.02,1439.37 844.5,1439.85 844.5,1460.15 844.02,1460.63 v1(844.02,1550)
MODE: J4.11 R15.1 U4.11 | length 771.8
  Top Layer w10: R15.1@947.56,745 J4.11@1295,745 ; J4.11@1300,750 1380,750 1525,895 1525,940 1570.47,985.47 U4.11@1570.47,1015.51
MODE_MCU: R15.2 U1.10 | length 1189.6
  Top Layer w10: v1(195,860) 195,855.32 206.99,843.32 794.12,843.32 841.68,843.32 892.44,792.56 R15.2@892.44,745 ; v1(195,1140) 328.7,1140 U1.10@328.86,1139.84
  Bottom Layer w10: v1(195,860) v1(195,1140)
NetC9_1: C9.1 U4.30 | length 133.6
  Top Layer w10: C9.1@1510,1313.05 1570.47,1252.58 U4.30@1570.47,1204.49
NetC9_2: C9.2 U4.31 | length 67.2
  Top Layer w10: C9.2@1513,1256 1550.79,1218.21 U4.31@1550.79,1204.49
